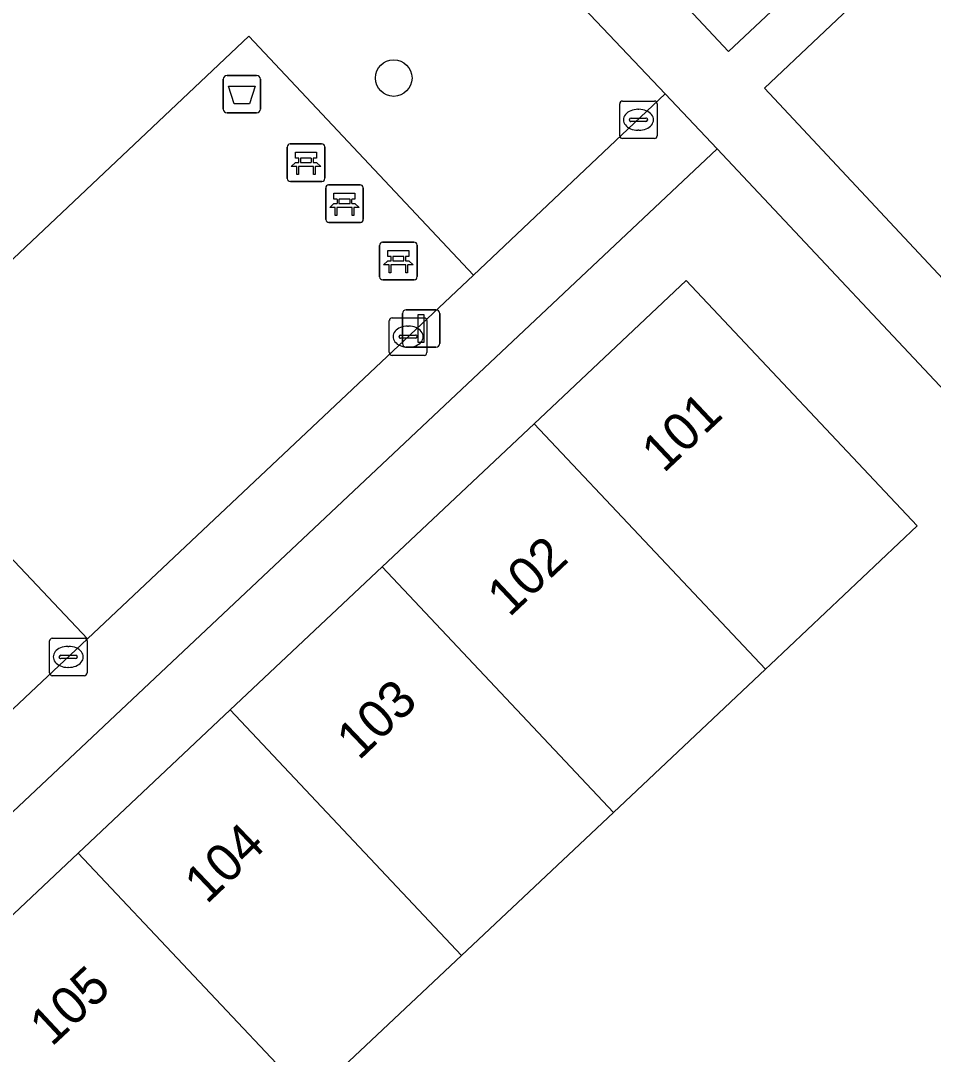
# Model space of a CAD drawing. Extents: x 162542 to 163147, y 380779 to 381521.
# Drawn here: x 162912.36 to 162936.71, y 381319.49 to 381347.07 of the extents above; entities that cross this region are included whole.
import ezdxf

# ---------------------------------------------------------------- set-up
doc = ezdxf.new("R2010")
doc.units = 0
for name, color, linetype in [('IMGEO_Afvalbak', 7, 'Continuous'), ('IMGEO_Bank', 7, 'Continuous'), ('IMGEO_Boom', 7, 'Continuous'), ('IMGEO_Erf', 7, 'Continuous'), ('IMGEO_Groenvoorziening', 7, 'Continuous'), ('IMGEO_Kolk', 7, 'Continuous'), ('IMGEO_Lichtmast', 7, 'Continuous'), ('IMGEO_Pand', 7, 'Continuous'), ('IMGEO_Pand_nummerreeks', 7, 'Continuous'), ('IMGEO_Terreindeel_halfverhard', 7, 'Continuous'), ('IMGEO_Voetpad_open', 7, 'Continuous')]:
    doc.layers.add(name, color=color, linetype=linetype)

msp = doc.modelspace()

# ---------------------------------------------------------------- linework, layer by layer
at = {"layer": 'IMGEO_Afvalbak'}
for p, q in [((162917.764, 381344.707), (162917.764, 381345.507)), ((162917.764, 381345.507), (162917.764, 381344.707)), ((162917.864, 381345.607), (162918.654, 381345.607)), ((162918.654, 381345.607), (162917.864, 381345.607)), ((162918.754, 381345.507), (162918.754, 381344.707)), ((162918.754, 381344.707), (162918.754, 381345.507)), ((162918.654, 381344.607), (162917.864, 381344.607)), ((162917.864, 381344.607), (162918.654, 381344.607))]:
    msp.add_line(p, q, dxfattribs=at)
msp.add_lwpolyline([(162917.907, 381345.321), (162918.611, 381345.321), (162918.462, 381344.851), (162918.056, 381344.851), (162917.907, 381345.321)], dxfattribs=at)
for centre, start, end in [((162917.864, 381345.507), 90, 180), ((162917.864, 381345.507), 90, 180), ((162918.654, 381345.507), 0, 90), ((162918.654, 381345.507), 360, 90), ((162917.864, 381344.707), 180, 270), ((162917.864, 381344.707), 180, 270), ((162918.654, 381344.707), 270, 0), ((162918.654, 381344.707), 270, 0)]:
    msp.add_arc(centre, 0.1, start, end, dxfattribs=at)
at = {"layer": 'IMGEO_Bank'}
for p, q in [((162919.472, 381342.857), (162919.472, 381343.698)), ((162919.472, 381343.698), (162919.472, 381342.857)), ((162919.547, 381343.782), (162920.388, 381343.782)), ((162920.388, 381343.782), (162919.547, 381343.782)), ((162920.472, 381343.707), (162920.472, 381342.866)), ((162920.472, 381342.866), (162920.472, 381343.707)), ((162920.169, 381343.18), (162919.776, 381343.18)), ((162919.781, 381343.288), (162919.781, 381343.394)), ((162919.825, 381343.394), (162919.825, 381343.288)), ((162920.113, 381343.4), (162919.831, 381343.4)), ((162919.831, 381343.282), (162920.113, 381343.282)), ((162920.119, 381343.288), (162920.119, 381343.394)), ((162920.163, 381343.394), (162920.163, 381343.288)), ((162920.397, 381342.782), (162919.556, 381342.782)), ((162919.556, 381342.782), (162920.397, 381342.782)), ((162920.498, 381341.763), (162920.498, 381342.604)), ((162920.498, 381342.604), (162920.498, 381341.763)), ((162920.573, 381342.688), (162921.414, 381342.688)), ((162921.414, 381342.688), (162920.573, 381342.688)), ((162921.498, 381342.613), (162921.498, 381341.772)), ((162921.498, 381341.772), (162921.498, 381342.613)), ((162921.195, 381342.086), (162920.802, 381342.086)), ((162920.807, 381342.194), (162920.807, 381342.3)), ((162920.851, 381342.3), (162920.851, 381342.194)), ((162921.139, 381342.306), (162920.857, 381342.306)), ((162920.857, 381342.188), (162921.139, 381342.188)), ((162921.145, 381342.194), (162921.145, 381342.3)), ((162921.189, 381342.3), (162921.189, 381342.194)), ((162921.423, 381341.688), (162920.582, 381341.688)), ((162920.582, 381341.688), (162921.423, 381341.688)), ((162921.935, 381340.232), (162921.935, 381341.073)), ((162921.935, 381341.073), (162921.935, 381340.232)), ((162922.01, 381341.157), (162922.851, 381341.157)), ((162922.851, 381341.157), (162922.01, 381341.157)), ((162922.935, 381341.082), (162922.935, 381340.241)), ((162922.935, 381340.241), (162922.935, 381341.082)), ((162922.244, 381340.663), (162922.244, 381340.769)), ((162922.288, 381340.769), (162922.288, 381340.663)), ((162922.576, 381340.775), (162922.294, 381340.775)), ((162922.582, 381340.663), (162922.582, 381340.769)), ((162922.626, 381340.769), (162922.626, 381340.663)), ((162922.632, 381340.555), (162922.239, 381340.555)), ((162922.294, 381340.657), (162922.576, 381340.657)), ((162922.86, 381340.157), (162922.019, 381340.157)), ((162922.019, 381340.157), (162922.86, 381340.157))]:
    msp.add_line(p, q, dxfattribs=at)
for points in [[(162919.775, 381343.4), (162919.689, 381343.4), (162919.689, 381343.561), (162920.252, 381343.561), (162920.252, 381343.4), (162920.169, 381343.4)], [(162919.719, 381343.18), (162919.577, 381343.18), (162919.689, 381343.282), (162919.775, 381343.282)], [(162919.769, 381343.173), (162919.769, 381342.966), (162919.726, 381342.966), (162919.726, 381343.173)], [(162920.169, 381343.282), (162920.252, 381343.282), (162920.364, 381343.18), (162920.225, 381343.18)], [(162920.219, 381343.173), (162920.219, 381342.966), (162920.175, 381342.966), (162920.175, 381343.173)], [(162920.801, 381342.306), (162920.715, 381342.306), (162920.715, 381342.467), (162921.278, 381342.467), (162921.278, 381342.306), (162921.195, 381342.306)], [(162920.745, 381342.086), (162920.603, 381342.086), (162920.715, 381342.188), (162920.801, 381342.188)], [(162920.795, 381342.079), (162920.795, 381341.872), (162920.752, 381341.872), (162920.752, 381342.079)], [(162921.195, 381342.188), (162921.278, 381342.188), (162921.39, 381342.086), (162921.251, 381342.086)], [(162921.245, 381342.079), (162921.245, 381341.872), (162921.201, 381341.872), (162921.201, 381342.079)], [(162922.238, 381340.775), (162922.152, 381340.775), (162922.152, 381340.936), (162922.715, 381340.936), (162922.715, 381340.775), (162922.632, 381340.775)], [(162922.182, 381340.555), (162922.04, 381340.555), (162922.152, 381340.657), (162922.238, 381340.657)], [(162922.232, 381340.548), (162922.232, 381340.341), (162922.189, 381340.341), (162922.189, 381340.548)], [(162922.632, 381340.657), (162922.715, 381340.657), (162922.827, 381340.555), (162922.688, 381340.555)], [(162922.682, 381340.548), (162922.682, 381340.341), (162922.638, 381340.341), (162922.638, 381340.548)]]:
    msp.add_lwpolyline(points, dxfattribs=at)
for centre, radius, start, end in [((162919.55, 381343.704), 0.0779, 92.4484, 184.2845), ((162919.55, 381343.704), 0.0779, 92.4484, 184.2845), ((162920.394, 381343.704), 0.0779, 2.4484, 94.2845), ((162920.394, 381343.704), 0.0779, 2.4484, 94.2845), ((162919.719, 381343.173), 0.00671, 2.8957, 87.1043), ((162919.776, 381343.173), 0.00671, 92.8957, 177.1043), ((162919.774, 381343.393), 0.00671, 2.8957, 87.1043), ((162919.774, 381343.289), 0.00671, 272.8957, 357.1043), ((162919.831, 381343.393), 0.00671, 92.8957, 177.1043), ((162919.831, 381343.289), 0.00671, 182.8957, 267.1043), ((162920.113, 381343.393), 0.00671, 2.8957, 87.1043), ((162920.113, 381343.289), 0.00671, 272.8957, 357.1043), ((162920.17, 381343.393), 0.00671, 92.8957, 177.1043), ((162920.17, 381343.289), 0.00671, 182.8957, 267.1043), ((162920.168, 381343.173), 0.00671, 2.8957, 87.1043), ((162920.225, 381343.173), 0.00671, 92.8957, 177.1043), ((162920.394, 381342.86), 0.0779, 272.4484, 4.2845), ((162920.394, 381342.86), 0.0779, 272.4484, 4.2845), ((162919.55, 381342.86), 0.0779, 182.4484, 274.2845), ((162919.55, 381342.86), 0.0779, 182.4484, 274.2845), ((162920.576, 381342.61), 0.0779, 92.4484, 184.2845), ((162920.576, 381342.61), 0.0779, 92.4484, 184.2845), ((162921.42, 381342.61), 0.0779, 2.4484, 94.2845), ((162921.42, 381342.61), 0.0779, 2.4484, 94.2845), ((162920.745, 381342.079), 0.00671, 2.8957, 87.1043), ((162920.802, 381342.079), 0.00671, 92.8957, 177.1043), ((162920.8, 381342.299), 0.00671, 2.8957, 87.1043), ((162920.8, 381342.195), 0.00671, 272.8957, 357.1043), ((162920.857, 381342.299), 0.00671, 92.8957, 177.1043), ((162920.857, 381342.195), 0.00671, 182.8957, 267.1043), ((162921.139, 381342.299), 0.00671, 2.8957, 87.1043), ((162921.139, 381342.195), 0.00671, 272.8957, 357.1043), ((162921.196, 381342.299), 0.00671, 92.8957, 177.1043), ((162921.196, 381342.195), 0.00671, 182.8957, 267.1043), ((162921.194, 381342.079), 0.00671, 2.8957, 87.1043), ((162921.251, 381342.079), 0.00671, 92.8957, 177.1043), ((162920.576, 381341.766), 0.0779, 182.4484, 274.2845), ((162920.576, 381341.766), 0.0779, 182.4484, 274.2845), ((162921.42, 381341.766), 0.0779, 272.4484, 4.2845), ((162921.42, 381341.766), 0.0779, 272.4484, 4.2845), ((162922.013, 381341.079), 0.0779, 92.4484, 184.2845), ((162922.013, 381341.079), 0.0779, 92.4484, 184.2845), ((162922.857, 381341.079), 0.0779, 2.4484, 94.2845), ((162922.857, 381341.079), 0.0779, 2.4484, 94.2845), ((162922.237, 381340.768), 0.00671, 2.8957, 87.1043), ((162922.237, 381340.664), 0.00671, 272.8957, 357.1043), ((162922.294, 381340.768), 0.00671, 92.8957, 177.1043), ((162922.294, 381340.664), 0.00671, 182.8957, 267.1043), ((162922.576, 381340.768), 0.00671, 2.8957, 87.1043), ((162922.576, 381340.664), 0.00671, 272.8957, 357.1043), ((162922.633, 381340.768), 0.00671, 92.8957, 177.1043), ((162922.633, 381340.664), 0.00671, 182.8957, 267.1043), ((162922.182, 381340.548), 0.00671, 2.8957, 87.1043), ((162922.239, 381340.548), 0.00671, 92.8957, 177.1043), ((162922.631, 381340.548), 0.00671, 2.8957, 87.1043), ((162922.688, 381340.548), 0.00671, 92.8957, 177.1043), ((162922.013, 381340.235), 0.0779, 182.4484, 274.2845), ((162922.013, 381340.235), 0.0779, 182.4484, 274.2845), ((162922.857, 381340.235), 0.0779, 272.4484, 4.2845), ((162922.857, 381340.235), 0.0779, 272.4484, 4.2845)]:
    msp.add_arc(centre, radius, start, end, dxfattribs=at)
at = {"layer": 'IMGEO_Boom'}
msp.add_circle((162922.31, 381345.539), 0.489, dxfattribs=at)
at = {"layer": 'IMGEO_Erf'}
msp.add_lwpolyline([(162942.956, 381330.887), (162939.759, 381327.928), (162937.622, 381330.249), (162940.788, 381333.18), (162938.258, 381335.857), (162930.94, 381343.649), (162873.818, 381289.875), (162880.071, 381283.181), (162886.067, 381276.815), (162886.269, 381276.967), (162890.823, 381281.229), (162891.956, 381280.018), (162891.424, 381279.52), (162892.33, 381278.552), (162888.308, 381274.789), (162889.625, 381273.425), (162889.429, 381273.239), (162902.331, 381259.587), (162950.027, 381304.513), (162959.44, 381313.384), (162948.902, 381324.556), (162946.542, 381327.046), (162943.123, 381330.71)], close=True, dxfattribs=at)
msp.add_lwpolyline([(162905.782, 381317.223), (162909.837, 381321.042), (162913.891, 381324.86), (162917.946, 381328.679), (162922.001, 381332.498), (162926.056, 381336.316), (162930.11, 381340.134), (162936.277, 381333.59), (162932.362, 381329.894), (162932.225, 381329.766), (162928.171, 381325.946), (162924.117, 381322.127), (162920.063, 381318.307)], dxfattribs=at)
at = {"layer": 'IMGEO_Groenvoorziening'}
for points in [[(162927.322, 381359.24), (162924.862, 381361.84), (162920.433, 381357.796), (162921.367, 381356.796), (162931.242, 381346.25), (162935.66, 381350.401)], [(162914.15, 381354.131), (162907.437, 381352.98), (162883.712, 381314.744), (162887.377, 381312.568), (162897.045, 381319.956), (162901.06, 381318.269), (162914.139, 381330.573), (162908.14, 381336.93), (162918.45, 381346.658), (162924.439, 381340.275), (162929.552, 381345.117), (162920.048, 381355.142)], [(162936.553, 381349.389), (162932.201, 381345.269), (162944.555, 381332.065), (162948.968, 381336.257)]]:
    msp.add_lwpolyline(points, close=True, dxfattribs=at)
at = {"layer": 'IMGEO_Kolk'}
for p, q in [((162928.339, 381343.998), (162928.339, 381344.85)), ((162928.414, 381344.924), (162929.266, 381344.924)), ((162929.34, 381344.85), (162929.34, 381343.998)), ((162928.827, 381344.704), (162928.852, 381344.704)), ((162928.598, 381344.418), (162928.598, 381344.43)), ((162929.036, 381344.381), (162928.638, 381344.381)), ((162928.641, 381344.467), (162929.039, 381344.467)), ((162929.082, 381344.43), (162929.082, 381344.418)), ((162928.85, 381344.144), (162928.825, 381344.144)), ((162929.266, 381343.924), (162928.414, 381343.924)), ((162922.194, 381338.213), (162922.194, 381339.065)), ((162922.269, 381339.139), (162923.121, 381339.139)), ((162923.195, 381339.065), (162923.195, 381338.213)), ((162922.682, 381338.919), (162922.707, 381338.919)), ((162922.453, 381338.633), (162922.453, 381338.645)), ((162922.891, 381338.596), (162922.493, 381338.596)), ((162922.496, 381338.682), (162922.894, 381338.682)), ((162922.937, 381338.645), (162922.937, 381338.633)), ((162922.705, 381338.359), (162922.68, 381338.359)), ((162923.121, 381338.139), (162922.269, 381338.139)), ((162913.128, 381329.667), (162913.128, 381330.519)), ((162913.203, 381330.593), (162914.055, 381330.593)), ((162914.129, 381330.519), (162914.129, 381329.667)), ((162913.616, 381330.373), (162913.641, 381330.373)), ((162913.387, 381330.087), (162913.387, 381330.099)), ((162913.825, 381330.05), (162913.427, 381330.05)), ((162913.43, 381330.136), (162913.828, 381330.136)), ((162913.871, 381330.099), (162913.871, 381330.087)), ((162913.639, 381329.813), (162913.614, 381329.813)), ((162914.055, 381329.593), (162913.203, 381329.593))]:
    msp.add_line(p, q, dxfattribs=at)
for points in [[(162928.339, 381343.998), (162928.339, 381344.85)], [(162928.414, 381344.924), (162929.266, 381344.924)], [(162929.34, 381344.85), (162929.34, 381343.998)], [(162929.266, 381343.924), (162928.414, 381343.924)], [(162922.194, 381338.213), (162922.194, 381339.065)], [(162922.269, 381339.139), (162923.121, 381339.139)], [(162923.195, 381339.065), (162923.195, 381338.213)], [(162923.121, 381338.139), (162922.269, 381338.139)], [(162913.128, 381329.667), (162913.128, 381330.519)], [(162913.203, 381330.593), (162914.055, 381330.593)], [(162914.129, 381330.519), (162914.129, 381329.667)], [(162914.055, 381329.593), (162913.203, 381329.593)]]:
    msp.add_lwpolyline(points, dxfattribs=at)
for centre, radius, start, end in [((162928.416, 381344.848), 0.0765, 91.552, 178.448), ((162928.416, 381344.848), 0.0765, 91.552, 178.448), ((162929.264, 381344.848), 0.0765, 1.552, 88.448), ((162929.264, 381344.848), 0.0765, 1.552, 88.448), ((162928.638, 381344.427), 0.0403, 85.8775, 175.7526), ((162928.635, 381344.417), 0.0366, 178.938, 274.7102), ((162929.039, 381344.424), 0.043, 264.8664, 352.4533), ((162929.043, 381344.429), 0.0386, 1.7309, 96.639), ((162928.416, 381344), 0.0765, 181.552, 268.448), ((162928.416, 381344), 0.0765, 181.552, 268.448), ((162929.264, 381344), 0.0765, 271.552, 358.448), ((162929.264, 381344), 0.0765, 271.552, 358.448), ((162922.271, 381339.063), 0.0765, 91.552, 178.448), ((162922.271, 381339.063), 0.0765, 91.552, 178.448), ((162923.119, 381339.063), 0.0765, 1.552, 88.448), ((162923.119, 381339.063), 0.0765, 1.552, 88.448), ((162922.493, 381338.642), 0.0403, 85.8775, 175.7526), ((162922.49, 381338.632), 0.0366, 178.938, 274.7102), ((162922.894, 381338.639), 0.043, 264.8664, 352.4533), ((162922.898, 381338.644), 0.0386, 1.7309, 96.639), ((162922.271, 381338.215), 0.0765, 181.552, 268.448), ((162922.271, 381338.215), 0.0765, 181.552, 268.448), ((162923.119, 381338.215), 0.0765, 271.552, 358.448), ((162923.119, 381338.215), 0.0765, 271.552, 358.448), ((162913.205, 381330.517), 0.0765, 91.552, 178.448), ((162913.205, 381330.517), 0.0765, 91.552, 178.448), ((162914.053, 381330.517), 0.0765, 1.552, 88.448), ((162914.053, 381330.517), 0.0765, 1.552, 88.448), ((162913.427, 381330.096), 0.0403, 85.8775, 175.7526), ((162913.424, 381330.086), 0.0366, 178.938, 274.7102), ((162913.828, 381330.093), 0.043, 264.8664, 352.4533), ((162913.832, 381330.098), 0.0386, 1.7309, 96.639), ((162913.205, 381329.669), 0.0765, 181.552, 268.448), ((162913.205, 381329.669), 0.0765, 181.552, 268.448), ((162914.053, 381329.669), 0.0765, 271.552, 358.448), ((162914.053, 381329.669), 0.0765, 271.552, 358.448)]:
    msp.add_arc(centre, radius, start, end, dxfattribs=at)
for centre, major_axis, ratio, start_param, end_param in [((162928.826, 381344.424), (-0.387, 0.002), 0.722429, 4.712389, 7.853982), ((162928.851, 381344.424), (-0.39, 0.002), 0.717154, 1.570796, 4.712389), ((162922.681, 381338.639), (-0.387, 0.002), 0.722429, 4.712389, 7.853982), ((162922.706, 381338.639), (-0.39, 0.002), 0.717154, 1.570796, 4.712389), ((162913.615, 381330.093), (-0.387, 0.002), 0.722429, 4.712389, 7.853982), ((162913.64, 381330.093), (-0.39, 0.002), 0.717154, 1.570796, 4.712389)]:
    msp.add_ellipse(centre, major_axis=major_axis, ratio=ratio, start_param=start_param, end_param=end_param, dxfattribs=at)
at = {"layer": 'IMGEO_Lichtmast'}
for p, q in [((162922.647, 381339.357), (162923.437, 381339.357)), ((162923.437, 381339.357), (162922.647, 381339.357)), ((162922.547, 381338.457), (162922.547, 381339.257)), ((162922.547, 381339.257), (162922.547, 381338.457)), ((162923.537, 381339.257), (162923.537, 381338.457)), ((162923.537, 381338.457), (162923.537, 381339.257)), ((162923.437, 381338.357), (162922.647, 381338.357)), ((162922.647, 381338.357), (162923.437, 381338.357))]:
    msp.add_line(p, q, dxfattribs=at)
msp.add_lwpolyline([(162922.967, 381339.232), (162923.117, 381339.232), (162923.117, 381338.482), (162922.967, 381338.482), (162922.967, 381339.232)], dxfattribs=at)
for centre, start, end in [((162922.647, 381339.257), 90, 180), ((162922.647, 381339.257), 90, 180), ((162923.437, 381339.257), 0, 90), ((162923.437, 381339.257), 360, 90), ((162922.647, 381338.457), 180, 270), ((162922.647, 381338.457), 180, 270), ((162923.437, 381338.457), 270, 0), ((162923.437, 381338.457), 270, 0)]:
    msp.add_arc(centre, 0.1, start, end, dxfattribs=at)
at = {"layer": 'IMGEO_Pand'}
for points in [[(162926.056, 381336.316), (162932.225, 381329.766), (162932.362, 381329.894), (162936.277, 381333.59), (162930.11, 381340.134)], [(162922.001, 381332.498), (162928.171, 381325.946), (162932.225, 381329.766), (162926.056, 381336.316)], [(162922.001, 381332.498), (162917.946, 381328.679), (162924.117, 381322.127), (162928.171, 381325.946)], [(162920.063, 381318.307), (162924.117, 381322.127), (162917.946, 381328.679), (162913.891, 381324.86)], [(162909.837, 381321.042), (162916.008, 381314.488), (162920.063, 381318.307), (162913.891, 381324.86)]]:
    msp.add_lwpolyline(points, close=True, dxfattribs=at)
at = {"layer": 'IMGEO_Terreindeel_halfverhard'}
msp.add_lwpolyline([(162914.139, 381330.573), (162924.439, 381340.275), (162918.45, 381346.658), (162908.14, 381336.93)], close=True, dxfattribs=at)
at = {"layer": 'IMGEO_Voetpad_open'}
for points in [[(162935.66, 381350.401), (162931.242, 381346.25), (162921.367, 381356.796)], [(162920.048, 381355.142), (162929.552, 381345.117), (162930.94, 381343.649), (162938.258, 381335.857), (162940.788, 381333.18), (162942.956, 381330.887), (162943.123, 381330.71), (162946.542, 381327.046), (162948.902, 381324.556), (162959.44, 381313.384)], [(162958.484, 381326.143), (162954.15, 381321.923), (162948.805, 381327.563), (162953.184, 381331.783), (162948.968, 381336.257), (162944.555, 381332.065), (162932.201, 381345.269), (162936.553, 381349.389)]]:
    msp.add_lwpolyline(points, dxfattribs=at)
msp.add_lwpolyline([(162930.94, 381343.649), (162929.552, 381345.117), (162924.439, 381340.275), (162914.139, 381330.573), (162901.06, 381318.269), (162897.045, 381319.956), (162887.377, 381312.568), (162883.712, 381314.744), (162882.08, 381312.238), (162887.971, 381305.961), (162872.439, 381291.347), (162873.818, 381289.875)], close=True, dxfattribs=at)

# ---------------------------------------------------------------- texts
at = {"layer": 'IMGEO_Pand_nummerreeks'}
for s, rotation, p in [('101', 43.3252, (162929.513, 381334.979)), ('102', 43.3634, (162925.394, 381331.133)), ('103', 43.698, (162921.382, 381327.311)), ('104', 43.6831, (162917.323, 381323.477)), ('105', 43.0694, (162913.185, 381319.674))]:
    msp.add_text(s, height=1, rotation=rotation, dxfattribs=at).set_placement(p)

doc.saveas('drawing.dxf')
